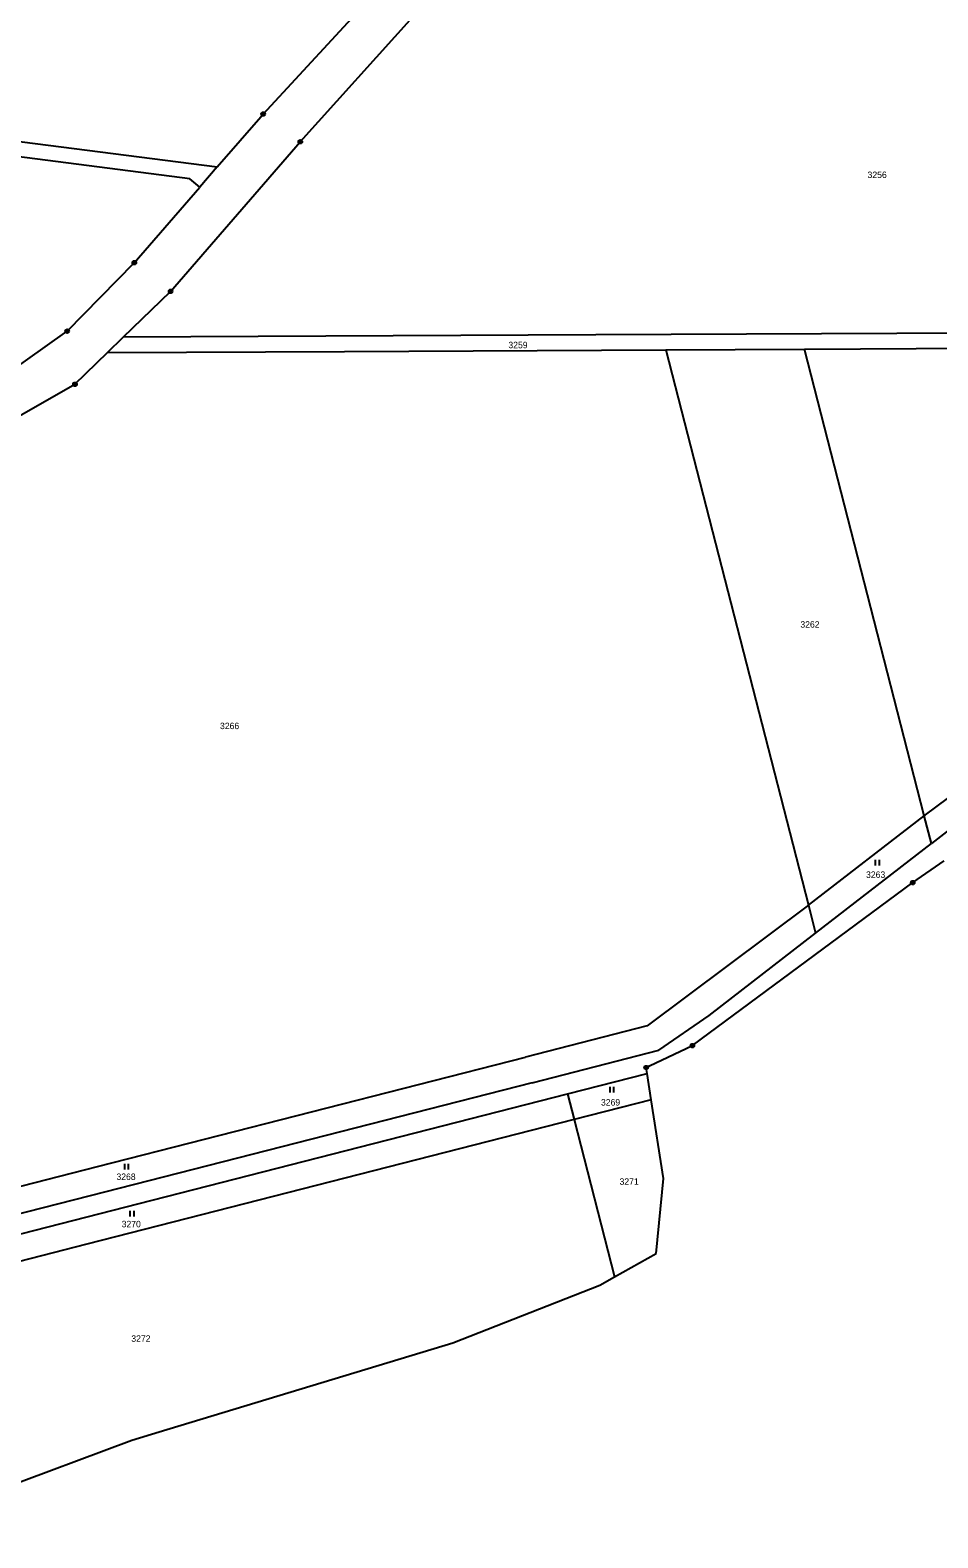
# Model space of a CAD drawing. Extents: x -618848 to -615803, y -1044450 to -1042254.
# Drawn here: x -617451.9 to -617212.5, y -1044446.5 to -1044049 of the extents above; entities that cross this region are included whole.
import ezdxf

# ---------------------------------------------------------------- set-up
doc = ezdxf.new("R2010")
doc.units = 0
doc.header["$LTSCALE"] = 0.68
for name, color, linetype, lineweight in [('1', 7, 'Continuous', 25), ('3', 7, 'Continuous', 25), ('8', 7, 'Continuous', 25)]:
    doc.layers.add(name, color=color, linetype=linetype, lineweight=lineweight)
doc.layers.add('2', color=7, linetype='Continuous')

msp = doc.modelspace()

# ---------------------------------------------------------------- linework, layer by layer
at = {"layer": '1'}
for p, q in [((-617390.41, -1044071.09), (-617360.44, -1044038.65)), ((-617380.62, -1044078.4), (-617350.88, -1044045.4)), ((-617565.03, -1044064.17), (-617402.5, -1044085.04)), ((-617409.75, -1044088.14), (-617565.49, -1044068.14)), ((-617402.5, -1044085.04), (-617390.41, -1044071.09)), ((-617414.83, -1044117.85), (-617380.62, -1044078.4)), ((-617402.5, -1044085.04), (-617407.14, -1044090.4)), ((-617407.14, -1044090.4), (-617409.75, -1044088.14)), ((-617424.39, -1044110.3), (-617407.14, -1044090.4)), ((-617442.1, -1044128.33), (-617424.39, -1044110.3)), ((-617427.29, -1044129.96), (-617414.83, -1044117.85)), ((-617458.31, -1044139.86), (-617442.1, -1044128.33)), ((-617302.68, -1044129.34), (-617427.29, -1044129.96)), ((-617178.08, -1044128.73), (-617302.68, -1044129.34)), ((-617431.43, -1044133.98), (-617427.29, -1044129.96)), ((-617431.43, -1044133.98), (-617368.99, -1044133.68)), ((-617368.99, -1044133.68), (-617284.24, -1044133.26)), ((-617284.24, -1044133.26), (-617247.69, -1044133.08)), ((-617284.24, -1044133.26), (-617246.62, -1044279.73)), ((-617247.69, -1044133.08), (-617178.06, -1044132.73)), ((-617216.07, -1044256.12), (-617247.69, -1044133.08)), ((-617440.05, -1044142.35), (-617431.43, -1044133.98)), ((-617489.29, -1044170.32), (-617440.05, -1044142.35)), ((-617216.07, -1044256.12), (-617180.13, -1044229.25)), ((-617246.62, -1044279.73), (-617216.07, -1044256.12)), ((-617214.19, -1044263.45), (-617216.07, -1044256.12)), ((-617204.19, -1044255.72), (-617214.19, -1044263.45)), ((-617244.74, -1044287.06), (-617214.19, -1044263.45)), ((-617219.1, -1044273.74), (-617210.78, -1044267.96)), ((-617277.21, -1044316.72), (-617219.1, -1044273.74)), ((-617246.62, -1044279.73), (-617289.13, -1044311.52)), ((-617246.62, -1044279.73), (-617244.74, -1044287.06)), ((-617272.8, -1044308.75), (-617244.74, -1044287.06)), ((-617289.13, -1044311.52), (-617321.2, -1044319.73)), ((-617286.05, -1044317.96), (-617272.8, -1044308.75)), ((-617434.14, -1044348.62), (-617321.2, -1044319.73)), ((-617319.46, -1044326.5), (-617286.05, -1044317.96)), ((-617288.49, -1044322.07), (-617277.21, -1044316.72)), ((-617310.12, -1044329.44), (-617289.16, -1044324.08)), ((-617289.41, -1044322.51), (-617288.95, -1044322.29)), ((-617289.16, -1044324.08), (-617289.41, -1044322.51)), ((-617288.07, -1044331.02), (-617289.16, -1044324.08)), ((-617288.95, -1044322.29), (-617288.49, -1044322.07)), ((-617319.46, -1044326.5), (-617432.24, -1044355.35)), ((-617426.93, -1044359.32), (-617310.12, -1044329.44)), ((-617310.12, -1044329.44), (-617308.38, -1044336.21)), ((-617288.07, -1044331.02), (-617308.38, -1044336.21)), ((-617284.82, -1044351.75), (-617288.07, -1044331.02)), ((-617308.38, -1044336.21), (-617436.92, -1044369.09)), ((-617308.38, -1044336.21), (-617297.77, -1044377.72)), ((-617547.07, -1044377.5), (-617434.14, -1044348.62)), ((-617286.8, -1044371.54), (-617284.82, -1044351.75)), ((-617432.24, -1044355.35), (-617545.02, -1044384.2)), ((-617543.74, -1044389.19), (-617426.93, -1044359.32)), ((-617436.92, -1044369.09), (-617565.47, -1044401.97)), ((-617297.77, -1044377.72), (-617286.8, -1044371.54)), ((-617340.38, -1044395.08), (-617301.66, -1044379.91)), ((-617301.66, -1044379.91), (-617297.77, -1044377.72)), ((-617417.8, -1044418.55), (-617340.38, -1044395.08)), ((-617425.02, -1044420.74), (-617417.8, -1044418.55)), ((-617493.98, -1044446.51), (-617425.02, -1044420.74))]:
    msp.add_line(p, q, dxfattribs=at)
at = {"layer": '3'}
for p, q in [((-617228.891, -1044269.2), (-617228.891, -1044267.7)), ((-617227.89, -1044269.2), (-617227.89, -1044267.7)), ((-617298.911, -1044329.09), (-617298.911, -1044327.59)), ((-617297.91, -1044329.09), (-617297.91, -1044327.59)), ((-617426.911, -1044349.38), (-617426.911, -1044347.88)), ((-617425.91, -1044349.38), (-617425.91, -1044347.88)), ((-617425.451, -1044361.81), (-617425.451, -1044360.31)), ((-617424.45, -1044361.81), (-617424.45, -1044360.31))]:
    msp.add_line(p, q, dxfattribs=at)
at = {"layer": '8'}
for centre, radius in [((-617390.41, -1044071.0899), 0.5), ((-617390.41, -1044071.0899), 0.0303), ((-617380.62, -1044078.3999), 0.5), ((-617380.62, -1044078.3999), 0.0303), ((-617424.39, -1044110.2999), 0.5), ((-617424.39, -1044110.2999), 0.0303), ((-617414.83, -1044117.8499), 0.5), ((-617414.83, -1044117.8499), 0.0303), ((-617442.1, -1044128.3299), 0.5), ((-617442.1, -1044128.3299), 0.0303), ((-617440.05, -1044142.3499), 0.5), ((-617440.05, -1044142.3499), 0.0303), ((-617219.1, -1044273.7399), 0.5), ((-617219.1, -1044273.7399), 0.0303), ((-617277.21, -1044316.7199), 0.5), ((-617277.21, -1044316.7199), 0.0303), ((-617289.41, -1044322.5099), 0.5), ((-617289.41, -1044322.5099), 0.0303)]:
    msp.add_circle(centre, radius, dxfattribs=at)

# ---------------------------------------------------------------- texts
at = {"layer": '2'}
for s, p in [('3256', (-617231.02, -1044087.965)), ('3259', (-617325.74, -1044132.845)), ('3262', (-617248.74, -1044206.515)), ('3266', (-617401.79, -1044233.275)), ('3263', (-617231.42, -1044272.495)), ('3269', (-617301.33, -1044332.525)), ('3268', (-617429.1, -1044352.145)), ('3271', (-617296.43, -1044353.415)), ('3270', (-617427.73, -1044364.625)), ('3272', (-617425.18, -1044394.815))]:
    msp.add_text(s, height=1.7, dxfattribs=at).set_placement(p)

doc.saveas('drawing.dxf')
